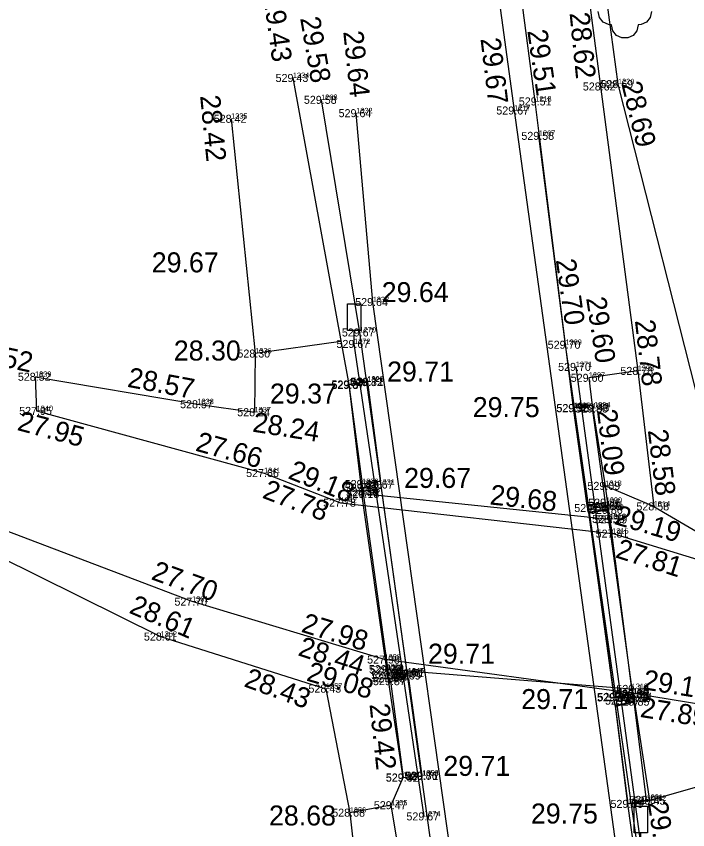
# Model space of a CAD drawing. Extents: x -866693 to -866303, y -1041966 to -1040244.
# Drawn here: x -866499.42 to -866474.26, y -1041765.62 to -1041735.13 of the extents above; entities that cross this region are included whole.
import ezdxf

# ---------------------------------------------------------------- set-up
doc = ezdxf.new("R2010")
doc.units = 0
for name, color, linetype in [('1 hrana zpevněné komunikace-plocha', 7, 'Continuous'), ('12 potok _kanál-břeh', 7, 'Continuous'), ('13 potok _kanál-dno', 7, 'Continuous'), ('14 zábradlí', 7, 'Continuous'), ('15 svodidlo', 7, 'Continuous'), ('16 žlabovka', 7, 'Continuous'), ('36 zeď opěrná', 7, 'Continuous'), ('37 propustek', 7, 'Continuous'), ('60 strom bez rozlišení', 7, 'Continuous'), ('7 hrana svah nahoře', 7, 'Continuous'), ('8 hrana svah dole', 7, 'Continuous'), ('82 informační tabule', 7, 'Continuous'), ('Bod', 7, 'Continuous'), ('Nadmořská výška', 7, 'Continuous'), ('Nadmořská výška_tisk', 7, 'Continuous'), ('Číslo bodu', 7, 'Continuous')]:
    doc.layers.add(name, color=color, linetype=linetype)

msp = doc.modelspace()

# ---------------------------------------------------------------- linework, layer by layer
at = {"layer": '1 hrana zpevněné komunikace-plocha'}
for p, q in [((-866486.959, -1041748.925), (-866486.469, -1041753.029)), ((-866485.731, -1041752.812), (-866485.768, -1041752.55)), ((-866486.42, -1041752.914), (-866486.457, -1041752.658)), ((-866485.537, -1041759.601), (-866476.358, -1041760.34))]:
    msp.add_line(p, q, dxfattribs=at)
for points in [[(-866521.136, -1041445.078), (-866508.392, -1041537.454), (-866498.773, -1041606.69), (-866494.1, -1041640.595), (-866489.402, -1041674.676), (-866486.72, -1041694.284), (-866486.072, -1041699.754), (-866485.271, -1041705.651), (-866480.766, -1041738.663), (-866470.416, -1041813.512), (-866469.678, -1041818.801), (-866468.328, -1041828.98), (-866464.804, -1041855.208), (-866460.868, -1041884.031), (-866456.109, -1041894.798), (-866454.046, -1041896.659), (-866450.549, -1041899.657), (-866442.256, -1041905.958), (-866433.526, -1041913.041), (-866423.347, -1041921.351)], [(-866481.925, -1041775.102), (-866486.062, -1041745.843), (-866486.68, -1041738.761)]]:
    msp.add_lwpolyline(points, dxfattribs=at)
at = {"layer": '12 potok _kanál-břeh'}
for p, q in [((-866498.714, -1041748.641), (-866492.632, -1041749.666)), ((-866492.632, -1041749.666), (-866490.492, -1041749.971)), ((-866475.529, -1041753.503), (-866477.346, -1041752.73)), ((-866475.529, -1041753.503), (-866472.409, -1041755.326)), ((-866500.125, -1041755.353), (-866494.011, -1041758.378)), ((-866494.011, -1041758.378), (-866487.817, -1041760.333)), ((-866473.345, -1041763.857), (-866475.673, -1041764.528))]:
    msp.add_line(p, q, dxfattribs=at)
at = {"layer": '13 potok _kanál-dno'}
for p, q in [((-866498.656, -1041749.922), (-866490.135, -1041752.251)), ((-866490.135, -1041752.251), (-866487.268, -1041753.363)), ((-866487.268, -1041753.363), (-866477.086, -1041754.517)), ((-866492.83, -1041757.067), (-866500.436, -1041754.175)), ((-866464.03, -1041758.542), (-866477.086, -1041754.517)), ((-866485.624, -1041759.244), (-866492.83, -1041757.067)), ((-866476.29, -1041760.51), (-866485.624, -1041759.244)), ((-866469.037, -1041761.703), (-866476.29, -1041760.51))]:
    msp.add_line(p, q, dxfattribs=at)
at = {"layer": '14 zábradlí'}
for p, q in [((-866484.138, -1041765.123), (-866486.76, -1041747.412)), ((-866478.454, -1041748.274), (-866476.017, -1041766.233))]:
    msp.add_line(p, q, dxfattribs=at)
at = {"layer": '15 svodidlo'}
for p, q in [((-866487.994, -1041738.261), (-866486.555, -1041746.98)), ((-866478.84, -1041747.443), (-866479.837, -1041739.609)), ((-866486.555, -1041746.98), (-866483.871, -1041766.266)), ((-866476.056, -1041766.848), (-866478.84, -1041747.443))]:
    msp.add_line(p, q, dxfattribs=at)
at = {"layer": '16 žlabovka'}
for p, q in [((-866485.848, -1041752.684), (-866486.443, -1041752.799)), ((-866477.851, -1041753.56), (-866477.305, -1041753.493)), ((-866485.418, -1041759.938), (-866484.828, -1041759.842)), ((-866476.69, -1041760.776), (-866476.213, -1041760.681))]:
    msp.add_line(p, q, dxfattribs=at)
at = {"layer": '36 zeď opěrná'}
for p, q in [((-866487.252, -1041747.317), (-866490.466, -1041747.768)), ((-866498.714, -1041748.641), (-866498.656, -1041749.922)), ((-866476.132, -1041748.419), (-866477.965, -1041748.675)), ((-866477.965, -1041748.675), (-866477.838, -1041749.712)), ((-866485.374, -1041764.702), (-866486.922, -1041764.982))]:
    msp.add_line(p, q, dxfattribs=at)
at = {"layer": '37 propustek'}
for p, q in [((-866486.263, -1041748.819), (-866486.959, -1041748.925)), ((-866486.959, -1041748.925), (-866486.457, -1041752.658)), ((-866486.26, -1041748.839), (-866486.263, -1041748.819)), ((-866486.26, -1041748.839), (-866485.768, -1041752.55)), ((-866478.514, -1041749.806), (-866478.532, -1041749.817)), ((-866478.026, -1041753.468), (-866478.532, -1041749.817)), ((-866477.838, -1041749.712), (-866478.514, -1041749.806)), ((-866478.008, -1041753.457), (-866478.514, -1041749.806)), ((-866477.332, -1041753.363), (-866477.838, -1041749.712)), ((-866477.838, -1041749.712), (-866477.346, -1041752.73)), ((-866486.457, -1041752.658), (-866486.462, -1041752.624)), ((-866486.457, -1041752.658), (-866485.768, -1041752.55)), ((-866486.42, -1041752.914), (-866486.469, -1041753.029)), ((-866486.42, -1041752.914), (-866485.731, -1041752.812)), ((-866485.456, -1041759.825), (-866486.42, -1041752.914)), ((-866484.768, -1041759.724), (-866485.731, -1041752.812)), ((-866477.346, -1041752.73), (-866477.192, -1041753.97)), ((-866485.537, -1041759.601), (-866486.469, -1041753.029)), ((-866477.181, -1041753.988), (-866486.469, -1041753.029)), ((-866477.35, -1041753.374), (-866478.026, -1041753.468)), ((-866478.008, -1041753.457), (-866478.026, -1041753.468)), ((-866477.974, -1041753.724), (-866478.026, -1041753.468)), ((-866477.332, -1041753.363), (-866478.008, -1041753.457)), ((-866477.332, -1041753.363), (-866477.35, -1041753.374)), ((-866477.35, -1041753.374), (-866477.273, -1041753.605)), ((-866477.273, -1041753.605), (-866477.974, -1041753.724)), ((-866477.974, -1041753.724), (-866477.965, -1041753.746)), ((-866477.974, -1041753.724), (-866477.02, -1041760.639)), ((-866477.965, -1041753.746), (-866477.264, -1041753.627)), ((-866477.965, -1041753.746), (-866477.011, -1041760.661)), ((-866477.273, -1041753.605), (-866477.264, -1041753.627)), ((-866476.31, -1041760.542), (-866477.264, -1041753.627)), ((-866477.192, -1041753.97), (-866477.086, -1041754.517)), ((-866477.192, -1041753.97), (-866477.181, -1041753.988)), ((-866477.181, -1041753.988), (-866476.358, -1041760.34)), ((-866484.923, -1041763.667), (-866485.537, -1041759.601)), ((-866485.456, -1041759.825), (-866484.768, -1041759.724)), ((-866485.384, -1041760.048), (-866484.717, -1041759.949)), ((-866484.717, -1041759.949), (-866484.217, -1041763.597)), ((-866485.384, -1041760.048), (-866485.401, -1041760.05)), ((-866485.401, -1041760.05), (-866484.923, -1041763.667)), ((-866477.02, -1041760.639), (-866476.319, -1041760.52)), ((-866477.011, -1041760.661), (-866476.31, -1041760.542)), ((-866476.358, -1041760.34), (-866476.29, -1041760.51)), ((-866476.319, -1041760.52), (-866476.31, -1041760.542)), ((-866476.278, -1041760.802), (-866476.319, -1041760.52)), ((-866475.673, -1041764.528), (-866476.29, -1041760.51)), ((-866477.02, -1041760.639), (-866477.011, -1041760.661)), ((-866476.978, -1041760.96), (-866477.02, -1041760.639)), ((-866476.978, -1041760.96), (-866476.278, -1041760.802)), ((-866476.969, -1041760.982), (-866476.269, -1041760.824)), ((-866476.278, -1041760.802), (-866476.269, -1041760.824)), ((-866475.801, -1041764.495), (-866476.269, -1041760.824)), ((-866476.978, -1041760.96), (-866476.969, -1041760.982)), ((-866476.978, -1041760.96), (-866476.496, -1041764.651)), ((-866476.501, -1041764.653), (-866476.969, -1041760.982)), ((-866484.923, -1041763.667), (-866484.217, -1041763.597)), ((-866476.501, -1041764.653), (-866475.801, -1041764.495)), ((-866475.673, -1041764.528), (-866476.496, -1041764.651)), ((-866475.801, -1041764.495), (-866475.673, -1041764.528)), ((-866476.496, -1041764.651), (-866476.501, -1041764.653))]:
    msp.add_line(p, q, dxfattribs=at)
at = {"layer": '60 strom bez rozlišení'}
msp.add_lwpolyline([(-866475.613, -1041734.952), (-866475.662, -1041735.169), (-866475.802, -1041735.343), (-866476.002, -1041735.439), (-866476.113, -1041735.452), (-866476.162, -1041735.669), (-866476.302, -1041735.843), (-866476.502, -1041735.939), (-866476.724, -1041735.939), (-866476.924, -1041735.843), (-866477.064, -1041735.669), (-866477.113, -1041735.452), (-866477.224, -1041735.439), (-866477.424, -1041735.343), (-866477.564, -1041735.169), (-866477.613, -1041734.952)], dxfattribs=at)
at = {"layer": '7 hrana svah nahoře'}
for p, q in [((-866481.373, -1041704.565), (-866476.87, -1041737.672)), ((-866479.973, -1041738.324), (-866484.319, -1041705.519)), ((-866489.054, -1041737.439), (-866486.959, -1041748.925)), ((-866476.87, -1041737.672), (-866472.409, -1041755.326)), ((-866478.532, -1041749.817), (-866479.973, -1041738.324)), ((-866485.374, -1041764.702), (-866484.923, -1041763.667)), ((-866483.644, -1041774.651), (-866485.374, -1041764.702)), ((-866475.236, -1041773.922), (-866476.496, -1041764.651))]:
    msp.add_line(p, q, dxfattribs=at)
at = {"layer": '8 hrana svah dole'}
for p, q in [((-866481.791, -1041704.717), (-866477.53, -1041737.756)), ((-866477.53, -1041737.756), (-866476.132, -1041748.419)), ((-866491.37, -1041738.967), (-866490.466, -1041747.768)), ((-866490.466, -1041747.768), (-866490.492, -1041749.971)), ((-866476.132, -1041748.419), (-866475.529, -1041753.503)), ((-866487.817, -1041760.333), (-866486.922, -1041764.982)), ((-866486.922, -1041764.982), (-866485.923, -1041774.166))]:
    msp.add_line(p, q, dxfattribs=at)
at = {"layer": '82 informační tabule'}
for points in [[(-866486.76, -1041747.412), (-866486.76, -1041746.912), (-866487.01, -1041746.912), (-866487.01, -1041745.912), (-866486.51, -1041745.912), (-866486.51, -1041746.912), (-866486.76, -1041746.912)], [(-866476.017, -1041766.233), (-866476.017, -1041765.733), (-866476.267, -1041765.733), (-866476.267, -1041764.733), (-866475.767, -1041764.733), (-866475.767, -1041765.733), (-866476.017, -1041765.733)]]:
    msp.add_lwpolyline(points, dxfattribs=at)
at = {"layer": 'Bod'}
for p, q in [((-866489.054, -1041737.439), (-866489.054, -1041737.439)), ((-866476.87, -1041737.672), (-866476.87, -1041737.672)), ((-866477.53, -1041737.756), (-866477.53, -1041737.756)), ((-866487.994, -1041738.261), (-866487.994, -1041738.261)), ((-866479.973, -1041738.324), (-866479.973, -1041738.324)), ((-866486.68, -1041738.761), (-866486.68, -1041738.761)), ((-866480.766, -1041738.663), (-866480.766, -1041738.663)), ((-866491.37, -1041738.967), (-866491.37, -1041738.967)), ((-866479.837, -1041739.609), (-866479.837, -1041739.609)), ((-866486.062, -1041745.843), (-866486.062, -1041745.843)), ((-866486.555, -1041746.98), (-866486.555, -1041746.98)), ((-866486.76, -1041747.412), (-866486.76, -1041747.412)), ((-866478.84, -1041747.443), (-866478.84, -1041747.443)), ((-866490.466, -1041747.768), (-866490.466, -1041747.768)), ((-866478.454, -1041748.274), (-866478.454, -1041748.274)), ((-866498.714, -1041748.641), (-866498.714, -1041748.641)), ((-866477.965, -1041748.675), (-866477.965, -1041748.675)), ((-866476.132, -1041748.419), (-866476.132, -1041748.419)), ((-866486.959, -1041748.925), (-866486.959, -1041748.925)), ((-866486.263, -1041748.819), (-866486.263, -1041748.819)), ((-866486.26, -1041748.839), (-866486.26, -1041748.839)), ((-866492.632, -1041749.666), (-866492.632, -1041749.666)), ((-866478.532, -1041749.817), (-866478.532, -1041749.817)), ((-866478.514, -1041749.806), (-866478.514, -1041749.806)), ((-866477.822, -1041749.829), (-866477.822, -1041749.829)), ((-866498.656, -1041749.922), (-866498.656, -1041749.922)), ((-866490.492, -1041749.971), (-866490.492, -1041749.971)), ((-866490.135, -1041752.251), (-866490.135, -1041752.251)), ((-866486.457, -1041752.658), (-866486.457, -1041752.658)), ((-866486.443, -1041752.799), (-866486.443, -1041752.799)), ((-866485.848, -1041752.684), (-866485.848, -1041752.684)), ((-866477.346, -1041752.73), (-866477.346, -1041752.73)), ((-866486.469, -1041753.029), (-866486.469, -1041753.029)), ((-866486.401, -1041752.972), (-866486.401, -1041752.972)), ((-866487.268, -1041753.363), (-866487.268, -1041753.363)), ((-866477.851, -1041753.56), (-866477.851, -1041753.56)), ((-866477.332, -1041753.363), (-866477.332, -1041753.363)), ((-866477.305, -1041753.493), (-866477.305, -1041753.493)), ((-866475.529, -1041753.503), (-866475.529, -1041753.503)), ((-866477.264, -1041753.627), (-866477.264, -1041753.627)), ((-866477.192, -1041753.97), (-866477.192, -1041753.97)), ((-866477.181, -1041753.988), (-866477.181, -1041753.988)), ((-866477.086, -1041754.517), (-866477.086, -1041754.517)), ((-866492.83, -1041757.067), (-866492.83, -1041757.067)), ((-866494.011, -1041758.378), (-866494.011, -1041758.378)), ((-866485.624, -1041759.244), (-866485.624, -1041759.244)), ((-866485.537, -1041759.601), (-866485.537, -1041759.601)), ((-866485.456, -1041759.825), (-866485.456, -1041759.825)), ((-866485.418, -1041759.938), (-866485.418, -1041759.938)), ((-866484.828, -1041759.842), (-866484.828, -1041759.842)), ((-866485.401, -1041760.05), (-866485.401, -1041760.05)), ((-866487.817, -1041760.333), (-866487.817, -1041760.333)), ((-866476.358, -1041760.34), (-866476.358, -1041760.34)), ((-866476.31, -1041760.542), (-866476.31, -1041760.542)), ((-866476.29, -1041760.51), (-866476.29, -1041760.51)), ((-866477.02, -1041760.639), (-866477.02, -1041760.639)), ((-866477.011, -1041760.661), (-866477.011, -1041760.661)), ((-866476.69, -1041760.776), (-866476.69, -1041760.776)), ((-866476.269, -1041760.824), (-866476.269, -1041760.824)), ((-866476.213, -1041760.681), (-866476.213, -1041760.681)), ((-866484.217, -1041763.597), (-866484.217, -1041763.597)), ((-866484.923, -1041763.663), (-866484.923, -1041763.663)), ((-866484.923, -1041763.667), (-866484.923, -1041763.667)), ((-866475.801, -1041764.495), (-866475.801, -1041764.495)), ((-866475.673, -1041764.528), (-866475.673, -1041764.528)), ((-866485.374, -1041764.702), (-866485.374, -1041764.702)), ((-866476.501, -1041764.653), (-866476.501, -1041764.653)), ((-866476.496, -1041764.651), (-866476.496, -1041764.651)), ((-866486.922, -1041764.982), (-866486.922, -1041764.982)), ((-866484.138, -1041765.123), (-866484.138, -1041765.123))]:
    msp.add_line(p, q, dxfattribs=at)

# ---------------------------------------------------------------- texts
at = {"layer": 'Nadmořská výška'}
for s, p in [('529.43', (-866489.701, -1041737.59)), ('528.62', (-866478.188, -1041737.91)), ('528.69', (-866477.529, -1041737.82)), ('529.58', (-866488.641, -1041738.41)), ('529.51', (-866480.588, -1041738.47)), ('529.64', (-866487.339, -1041738.91)), ('529.67', (-866481.429, -1041738.81)), ('528.42', (-866492.02, -1041739.12)), ('529.58', (-866480.491, -1041739.76)), ('529.64', (-866486.719, -1041745.99)), ('529.67', (-866487.219, -1041747.13)), ('529.67', (-866487.419, -1041747.56)), ('529.70', (-866479.504, -1041747.59)), ('528.30', (-866491.132, -1041747.92)), ('529.70', (-866479.114, -1041748.42)), ('528.78', (-866476.78, -1041748.57)), ('528.52', (-866499.36, -1041748.79)), ('529.82', (-866486.911, -1041748.99)), ('529.71', (-866486.878, -1041748.97)), ('529.60', (-866478.641, -1041748.83)), ('529.37', (-866487.611, -1041749.08)), ('529.87', (-866487.601, -1041749.1)), ('528.57', (-866493.28, -1041749.82)), ('527.95', (-866499.311, -1041750.07)), ('528.24', (-866491.14, -1041750.12)), ('529.75', (-866479.181, -1041749.97)), ('529.90', (-866479.175, -1041749.96)), ('529.88', (-866478.471, -1041749.98)), ('529.43', (-866478.421, -1041749.94)), ('527.66', (-866490.806, -1041752.4)), ('529.87', (-866487.111, -1041752.81)), ('529.66', (-866487.107, -1041752.95)), ('529.67', (-866486.509, -1041752.83)), ('529.09', (-866478.015, -1041752.88)), ('528.50', (-866487.062, -1041753.12)), ('529.18', (-866487.042, -1041753.18)), ('527.78', (-866487.92, -1041753.51)), ('529.86', (-866477.989, -1041753.51)), ('529.68', (-866478.509, -1041753.71)), ('529.66', (-866477.977, -1041753.64)), ('529.86', (-866477.919, -1041753.78)), ('528.58', (-866476.18, -1041753.65)), ('528.59', (-866477.841, -1041754.12)), ('529.19', (-866477.753, -1041754.14)), ('527.81', (-866477.707, -1041754.67)), ('527.70', (-866493.492, -1041757.22)), ('528.61', (-866494.635, -1041758.53)), ('527.98', (-866486.271, -1041759.39)), ('529.08', (-866486.204, -1041759.75)), ('528.44', (-866486.16, -1041759.79)), ('529.90', (-866485.425, -1041759.92)), ('529.71', (-866485.358, -1041759.9)), ('529.86', (-866486.119, -1041759.98)), ('529.68', (-866486.079, -1041760.09)), ('529.87', (-866486.051, -1041760.2)), ('529.69', (-866485.49, -1041759.99)), ('528.43', (-866488.47, -1041760.48)), ('529.18', (-866476.932, -1041760.49)), ('529.83', (-866477.661, -1041760.81)), ('529.71', (-866477.638, -1041760.79)), ('529.85', (-866476.961, -1041760.69)), ('527.89', (-866476.941, -1041760.66)), ('529.65', (-866476.869, -1041760.83)), ('529.66', (-866477.357, -1041760.93)), ('529.85', (-866476.921, -1041760.97)), ('529.87', (-866485.571, -1041763.81)), ('529.42', (-866485.571, -1041763.82)), ('529.86', (-866484.859, -1041763.74)), ('529.71', (-866484.838, -1041763.75)), ('529.75', (-866477.151, -1041764.8)), ('529.87', (-866477.151, -1041764.8)), ('529.87', (-866476.451, -1041764.65)), ('529.45', (-866476.321, -1041764.68)), ('528.68', (-866487.578, -1041765.13)), ('529.47', (-866486.021, -1041764.85)), ('529.67', (-866484.799, -1041765.27))]:
    msp.add_text(s, height=0.3, dxfattribs=at).set_placement(p)
at = {"layer": 'Nadmořská výška_tisk'}
for s, rotation, p in [('29.43', 277.7508, (-866490.158, -1041734.39)), ('29.58', 279.7877, (-866488.784, -1041735.2)), ('28.62', 275.6704, (-866478.686, -1041735.006)), ('29.64', 276.0325, (-866487.168, -1041735.702)), ('29.51', 278.1431, (-866480.269, -1041735.67)), ('29.67', 276.9552, (-866482.025, -1041735.969)), ('28.69', 283.7183, (-866476.747, -1041737.661)), ('28.42', 275.5697, (-866492.531, -1041738.11)), ('29.70', 278.1956, (-866479.204, -1041744.263)), ('29.60', 278.6602, (-866478.067, -1041745.693)), ('28.78', 276.6178, (-866476.238, -1041746.535)), ('28.52', 347.649, (-866501.342, -1041747.949)), ('28.57', 349.4902, (-866495.285, -1041749.014)), ('29.09', 277.0302, (-866477.662, -1041749.894)), ('27.95', 345.0036, (-866499.417, -1041750.632)), ('28.24', 351.0378, (-866490.595, -1041750.694)), ('27.66', 344.4355, (-866492.739, -1041751.405)), ('28.58', 277.1128, (-866475.755, -1041750.647)), ('29.18', 337.7176, (-866489.273, -1041752.433)), ('27.78', 338.8422, (-866490.234, -1041753.167)), ('29.68', 353.7805, (-866481.693, -1041753.424)), ('29.19', 343.6221, (-866477.046, -1041754.153)), ('27.81', 342.3701, (-866477, -1041755.404)), ('27.70', 340.0084, (-866494.399, -1041756.222)), ('28.61', 336.6052, (-866495.228, -1041757.478)), ('27.98', 342.8702, (-866488.775, -1041758.193)), ('28.44', 342.0468, (-866488.897, -1041759.075)), ('29.08', 343.6246, (-866488.58, -1041760.021)), ('28.43', 339.9605, (-866490.924, -1041760.236)), ('29.18', 350.952, (-866475.967, -1041760.351)), ('27.89', 350.8885, (-866476.068, -1041761.389)), ('29.42', 276.0697, (-866486.183, -1041760.917)), ('29.45', 278.6602, (-866475.757, -1041764.599))]:
    msp.add_text(s, height=0.75, rotation=rotation, dxfattribs=at).set_placement(p)
for s, p in [('29.67', (-866494.342, -1041744.727)), ('29.64', (-866485.725, -1041745.843)), ('28.30', (-866493.516, -1041748.032)), ('29.71', (-866485.524, -1041748.819)), ('29.37', (-866489.913, -1041749.645)), ('29.75', (-866482.314, -1041750.153)), ('29.67', (-866484.885, -1041752.807)), ('29.71', (-866483.989, -1041759.395)), ('29.71', (-866480.496, -1041761.097)), ('29.71', (-866483.415, -1041763.601)), ('28.68', (-866489.949, -1041765.46)), ('29.75', (-866480.132, -1041765.386))]:
    msp.add_text(s, height=0.75, dxfattribs=at).set_placement(p)
at = {"layer": 'Číslo bodu'}
for s, p in [('1334', (-866489.054, -1041737.439)), ('1219', (-866477.53, -1041737.756)), ('1220', (-866476.87, -1041737.672)), ('1268', (-866487.994, -1041738.261)), ('1218', (-866479.973, -1041738.324)), ('1332', (-866486.68, -1041738.761)), ('1217', (-866480.766, -1041738.663)), ('1335', (-866491.37, -1041738.967)), ('1267', (-866479.837, -1041739.609)), ('1333', (-866486.062, -1041745.843)), ('1270', (-866486.555, -1041746.98)), ('1272', (-866486.76, -1041747.412)), ('1269', (-866478.84, -1041747.443)), ('1336', (-866490.466, -1041747.768)), ('1271', (-866478.454, -1041748.274)), ('1298', (-866476.132, -1041748.419)), ('1339', (-866498.714, -1041748.641)), ('1325', (-866486.263, -1041748.819)), ('1326', (-866486.26, -1041748.839)), ('1297', (-866477.965, -1041748.675)), ('1328', (-866486.959, -1041748.925)), ('1327', (-866486.949, -1041748.947)), ('1338', (-866492.632, -1041749.666)), ('1296', (-866478.514, -1041749.806)), ('1294', (-866477.765, -1041749.79)), ('1340', (-866498.656, -1041749.922)), ('1337', (-866490.492, -1041749.971)), ('1295', (-866478.532, -1041749.817)), ('1293', (-866477.822, -1041749.829)), ('1341', (-866490.135, -1041752.251)), ('1329', (-866486.457, -1041752.658)), ('1330', (-866486.443, -1041752.799)), ('1331', (-866485.848, -1041752.684)), ('1318', (-866477.346, -1041752.73)), ('1344', (-866486.469, -1041753.029)), ('1343', (-866486.401, -1041752.972)), ('1342', (-866487.268, -1041753.363)), ('1290', (-866477.332, -1041753.363)), ('1292', (-866477.851, -1041753.56)), ('1291', (-866477.305, -1041753.493)), ('1289', (-866477.264, -1041753.627)), ('1314', (-866475.529, -1041753.503)), ('1316', (-866477.192, -1041753.97)), ('1317', (-866477.181, -1041753.988)), ('1315', (-866477.086, -1041754.517)), ('1361', (-866492.83, -1041757.067)), ('1362', (-866494.011, -1041758.378)), ('1358', (-866485.624, -1041759.244)), ('1360', (-866485.537, -1041759.601)), ('1359', (-866485.512, -1041759.641)), ('1345', (-866485.456, -1041759.825)), ('1350', (-866484.828, -1041759.842)), ('1347', (-866484.761, -1041759.772)), ('1346', (-866484.744, -1041759.753)), ('1349', (-866485.418, -1041759.938)), ('1348', (-866485.401, -1041760.05)), ('1357', (-866487.817, -1041760.333)), ('1313', (-866476.358, -1041760.34)), ('1287', (-866477.02, -1041760.639)), ('1288', (-866477.011, -1041760.661)), ('1285', (-866476.69, -1041760.776)), ('1286', (-866476.31, -1041760.542)), ('1312', (-866476.29, -1041760.51)), ('1284', (-866476.213, -1041760.681)), ('1283', (-866476.269, -1041760.824)), ('1351', (-866484.923, -1041763.663)), ('1352', (-866484.923, -1041763.667)), ('1353', (-866484.217, -1041763.597)), ('1354', (-866484.197, -1041763.591)), ('1355', (-866485.374, -1041764.702)), ('1280', (-866476.501, -1041764.653)), ('1279', (-866476.496, -1041764.651)), ('1281', (-866475.801, -1041764.495)), ('1282', (-866475.673, -1041764.528)), ('1356', (-866486.922, -1041764.982)), ('1274', (-866484.138, -1041765.123))]:
    msp.add_text(s, height=0.2, dxfattribs=at).set_placement(p)

doc.saveas('drawing.dxf')
